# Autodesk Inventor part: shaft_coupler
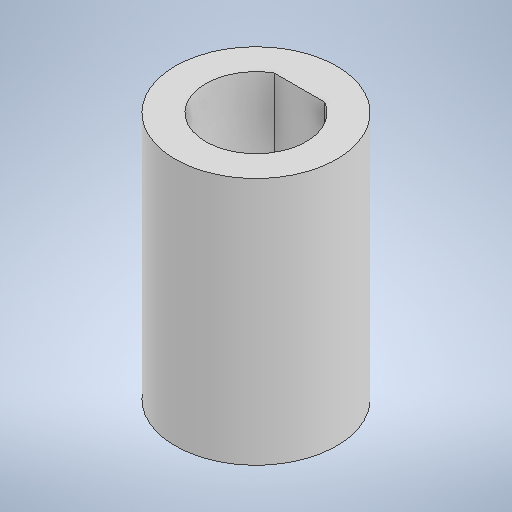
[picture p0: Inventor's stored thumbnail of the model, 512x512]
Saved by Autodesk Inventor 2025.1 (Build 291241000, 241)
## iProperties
Created: 2025-03
Part Number: shaft_coupler
Material: Genérico
Document SubType Name: Modeling
Designer: Usuario
Density: 1 g/cm^3
Appearance: Valor por defecto
Author: Usuario
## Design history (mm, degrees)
sketch "Boceto1"
  geometry: L1 (0, -4.05)-(0, -3.5); L2 (0, -3.5)-(2.038, -3.5); L3 (0, -3.5)-(-2.038, -3.5); C1 r 6.5 at (0, 0); A1 r 4.05 centre (0, 0) between (2.038, -3.5) and (-2.038, -3.5); 1 further point
  constraints: 6 end point, 2 centre point, 2 coincident, 2 point on circle, 1 perpendicular, 1 point on line, 1 vertical
  dimensions: "d0" = 8.1 diameter of A1; "d1" = 13 diameter of C1; "d2" = 0.55 distance of L1.start L1.end
extrude "shaft_coupler" new body sketch "Boceto1" distance "d3" = 20; taper "d4" = 0 deg
node "Sólido1"
